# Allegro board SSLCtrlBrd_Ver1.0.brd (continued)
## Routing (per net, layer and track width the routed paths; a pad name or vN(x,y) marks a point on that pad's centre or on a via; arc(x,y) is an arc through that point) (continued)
N16217582: length 4.1
  TOP w0.152: C15.1 44.4,36.83 44.4,34.82 43.99,34.42 U4.2
N16217594: length 2.2
  TOP w0.152: U4.6 40.4,31.82 C19.1
N16217668: length 2.3
  TOP w0.152: U4.4 40.65,33.12 C17.1
N16217676: length 4.4
  TOP w0.152: U4.3 41.6,33.77 41.15,34.21 39.5,34.21 C11.2
N16217680: length 2.2
  TOP w0.152: U4.1 40.4,35.07 C11.1
N16217684: length 4.2
  TOP w0.152: C17.2 39.5,32.59 40.95,32.59 41.07,32.47 U4.5
N16222454: length 11.5
  TOP w0.152: D4.2 93.42,57.06 v1(93.42,57.89) ; D4.2 94.97,57.01 R28.1 C46.1 95.46,56.16 96.83,56.16 97.14,55.85 U18.1 ; D4.2 93.26,56.9 91.77,56.9 91.06,56.18 J5.2
  BOTTOM w0.152: TP6.1 v1(93.42,57.89)
N16222490: length 9.3
  TOP w0.152: v1(51.63,9.02) 50.98,9.66 49.75,9.66 49.14,10.27 U10.8
  BOTTOM w0.152: RP2.1 RP1.8 51.63,9.99 v1(51.63,9.02)
N16222522: length 6.9
  TOP w0.152: v1(52.44,9.06) 52.44,10.12 51.68,10.88 U10.7
  BOTTOM w0.152: RP1.7 52.43,9.06 v1(52.44,9.06) 52.43,9.05 RP2.2
N16222576: length 7
  TOP w0.152: U10.6 54.22,11.11 53.25,10.15 v1(53.25,9.06)
  BOTTOM w0.152: RP2.3 53.25,9.05 v1(53.25,9.06) 53.25,9.06 RP1.6
N16222640: length 8.6
  TOP w0.152: U10.5 56.76,10.2 56.19,9.63 54.64,9.63 v1(54.07,9.06)
  BOTTOM w0.152: RP2.4 54.06,9.05 v1(54.07,9.06) 54.06,9.06 RP1.5
N16223004: length 5.5
  TOP w0.305: R20.2 133.92,16.74 U14.1 R22.1
N16223050: length 6.2
  TOP w0.152: J7.1 12.45,96.42 R30.1
  BOTTOM w0.152: J7.1 11.39,97.52 TP7.1
N16223096: length 5.5
  TOP w0.152: U20.3 56.16,46.15 R39.2 57.84,46.61 C49.1 R41.2
N16223166: length 4.5
  TOP w0.254: R19.1 45.39,48.5 R18.2 45.62,50.38 U9.4
N16223316: length 4.4
  BOTTOM w0.152: TP8.1 9.97,96.09 J7.2 11.45,94.6 Q3.3
N16223472: length 3.2
  TOP w0.33: U9.1 46.94,54.19 45.95,53.2 C34.2
N16223708: length 8.4
  TOP w0.305: R24.1 U14.2 131.21,15.67 133,13.89 R21.2
N16223800: length 16.8
  TOP w0.305: C43.1 128.25,13.19 ; 128.25,13.19 133.67,13.19 134.29,12.57 136.6,12.57 136.95,12.92 R21.1 R20.1 136.31,16.02 Q2.3 ; 128.25,13.19 U14.4
N16223854: length 1.6
  TOP w0.254: R42.1 D6.1
N16223890: length 21.9
  TOP w0.152: v1(56.82,17.09) 74.27,17.09 v1(75.02,16.35)
  BOTTOM w0.152: U13.9 76.34,16.35 v1(75.02,16.35) ; U11.10 v1(56.82,17.09)
N16224232: length 1.9
  TOP w0.152: U16.1 109.05,41.83 R26.1
N16224936: length 62.6
  TOP w0.203: v1(121.13,49.68) 121.13,43.51 127.03,37.62 130.23,37.62 U22.3
  BOTTOM w0.152: J9.6 132.92,82.42 127,76.5 121.9,76.5 120.3,74.9 120.3,61.99 118.24,59.93 118.24,57 120.37,54.86 120.37,52.3 119.46,51.38 119.46,50.11 119.89,49.68 121.13,49.68 v1(121.13,49.68)
N16225198: length 3.2
  BOTTOM w0.152: R32.2 15.14,92.39 R33.2 14.09,93.45 Q3.1
N16225308: length 6.4
  BOTTOM w0.254: TP9.1 J8.1 C50.1 R36.1
N16225518: length 4.9
  BOTTOM w0.254: R40.2 J8.3 TP10.1
N16225732: length 1.7
  TOP w0.152: R27.1 109.07,46.84 U17.1
N16226050: length 2.3
  TOP w0.152: D3.1 95.89,38.1 R23.1
N16226124: length 3.3
  TOP w0.152: R34.1 57.86,43.21 R37.2 56.21,43.23 U20.1
N16231004: length 12.9
  BOTTOM w0.152: RP7.6 51.89,97.87 51.49,97.46 TP14.1 51.44,95.53 J10.2 51.44,92 51.67,91.77 53.9,91.77 55.22,90.45 RP8.8
N16231012: length 16.7
  BOTTOM w0.152: RP7.7 50.42,98.68 49.05,97.31 TP15.1 48.94,95.47 J10.3 48.94,92.95 50.47,91.41 53.44,91.41 54.41,90.45 RP8.7
N16231068: length 21.6
  BOTTOM w0.152: RP7.8 47.8,99.49 46.41,98.09 TP16.1 46.41,93.42 J10.4 46.44,93.16 48.57,91.03 52.81,91.03 53.6,90.25 RP8.6
N16231202: length 12
  BOTTOM w0.152: RP9.6 111.05,97.41 110.64,97 TP22.1 110.64,93.48 111.99,92.13 114.3,92.13 114.89,91.54 RP10.8
N16231224: length 16.3
  BOTTOM w0.152: RP9.7 109.25,98.22 108.21,97.18 TP23.1 108.21,93.43 J12.3 109.9,91.72 113.49,91.72 114.07,91.14 RP10.7
N16231228: length 21.1
  BOTTOM w0.152: RP9.8 107.01,99.03 105.7,97.73 TP24.1 105.7,93.42 105.7,93.42 107.81,91.31 113.08,91.31 113.26,91.14 RP10.6
N16231344: length 5
  BOTTOM w0.152: J13.2 121.9,92.87 R70.2
  BOTTOM w0.254: TP28.1 123.4,96.28 J13.2
N16231348: length 53.2
  TOP w0.152: U28.3 105.29,44.78 105.89,45.39 105.89,54.03 v1(106.07,54.2)
  BOTTOM w0.152: v1(106.07,54.2) 106.66,54.79 106.66,64.21 113.01,70.56 113.01,75.64 120.06,82.69 D19.3 120.06,89.9 R71.1
N16231352: length 4.8
  BOTTOM w0.152: J13.4 120.42,93.36 R71.2
  BOTTOM w0.254: J13.4 119.4,96.31 TP29.1
N16231410: length 33.7
  TOP w0.152: v2(108.92,85.88) 108.97,85.88 109.02,85.83 ; C64.2 113.68,71.82 124.61,82.75 124.61,87.15 123.6,88.16 120.86,88.16 120.83,88.19
  TOP w0.254: C64.2 107.94,70.39 C68.2 107.82,70.21 107.24,70.21 106.43,71.02 U26.11
  vias: v2(93.35,86.64) v2(93.32,86.03) v2(93.98,86.66) v2(93.98,86.03) v2(94.67,86.64) v2(94.62,86) v2(99.52,86.74) v2(99.49,86) v2(100.23,86.74) v2(100.26,86) v2(100.94,86.72) v2(100.97,85.98) v2(106.07,86.66) v2(106.07,85.95) v2(106.78,86.66) v2(106.78,85.93) v2(107.47,85.95) v2(107.5,86.64) v2(108.08,88.77) v2(108.1,88.09) v2(108.1,87.4) v2(108.18,85.95) v2(108.21,86.64) v2(108.79,88.77) v2(108.79,88.09) v2(108.82,87.38) v2(108.94,86.61)
N16231448: length 7.4
  TOP w0.152: C66.2 109.45,65.13 R62.2 108.64,67.36 107.04,67.36 106.15,68.25 106.15,69.27 105.9,69.52 U26.8
N16231582: length 55.7
  TOP w0.152: v1(106.66,53.52) 106.28,53.14 106.28,44.73 104.45,42.9 U28.1
  BOTTOM w0.152: R70.1 121.9,89.6 D18.3 122.52,84.42 113.44,75.34 113.44,70.31 107.11,63.98 107.11,53.98 v1(106.66,53.52)
N16231708: length 24.7
  TOP w0.254: Q5.2 v1(39.12,78.87) ; v1(38.64,73.41) 37.54,73.41 37.27,73.13 U23.15
  BOTTOM w0.254: v1(39.12,78.87) 38.03,77.77 31.5,77.77 30.94,77.22 30.94,75.26 32.79,73.41 v1(38.64,73.41)
N16231980: length 3.4
  TOP w0.152: C63.2 107.34,68.17 106.63,68.88 106.63,69.42 106.04,70.02 U26.9
N16231984: length 5.2
  TOP w0.152: U26.10 106.04,70.52 106.18,70.37 106.19,70.37 106.99,69.57 106.99,69.14 107.16,68.96 108.6,68.96 C63.1
N16232020: length 3.4
  TOP w0.152: U26.25 100.07,71.02 99.54,71.55 99.54,72.67 99.26,72.95 R59.2
N16232070: length 13.7
  TOP w0.152: R62.1 R61.2 104.8,66.55 104.35,66.09 ; 103.3,66.09 102.34,66.09 102.06,66.37 102.06,67.21 101.88,67.39 101.88,67.92 102.02,68.05 U26.2 ; 103.3,66.09 104.35,66.09 ; 103.3,66.09 103.02,66.38 U26.4 ; 104.35,66.09 104.27,66.17 104.27,67.82 104.02,68.07 U26.6
N16232434: length 2.4
  TOP w0.152: C64.1 106.73,71.82 106.43,71.53 105.44,71.53 U26.12
N16232510: length 3.6
  TOP w0.254: R60.2 94.59,81.97 Q7.4
N16232530: length 8.8
  TOP w0.254: R60.1 97.36,76.73 99.37,74.73 100.99,74.73 101.48,74.24 101.48,73.42 U26.21
N16232652: length 4.5
  TOP w0.254: R63.1 100.84,76.05 101.09,75.79 102.03,75.79 102.52,75.31 U26.19
N16232660: length 3.7
  TOP w0.254: Q8.4 100.84,81.97 R63.2
N16232730: length 7.7
  BOTTOM w0.254: R57.2 25.58,99.85 28.27,97.16 TP20.1 28.23,96.24 J11.2
N16232734: length 68.2
  TOP w0.152: U25.3 42.17,43.79 v1(41.07,44.88)
  BOTTOM w0.152: R58.1 22.25,98.22 21.24,97.21 D13.3 20.94,95.87 29.49,87.33 29.49,68.74 30.89,67.34 30.89,65.74 32.79,63.83 34.01,63.83 41.51,56.34 41.51,48.08 41.07,47.65 v1(41.07,44.88)
N16232738: length 4
  BOTTOM w0.254: J11.4 24.23,96.29 TP21.1 24.51,96.57 R58.2
N16232790: length 5.9
  TOP w0.254: R64.1 104.9,76.56 103.52,75.17 U26.17
N16232794: length 3.8
  TOP w0.254: Q9.4 107.04,81.97 R64.2
N16232838: length 19.7
  TOP w0.254: U26.16 104.02,74.4 v1(104.5,74.88) ; Q7.2 v1(92.09,78.38)
  BOTTOM w0.254: v1(104.5,74.88) 104.5,75.84 102.57,77.77 96.98,77.77 96.37,78.38 v1(92.09,78.38)
N16232850: length 14.4
  TOP w0.254: Q8.2 v1(98.27,78.51) ; v1(105.21,74.45) 104.52,73.76 U26.15
  BOTTOM w0.254: v1(98.27,78.51) 98.3,78.54 102.64,78.54 105.29,75.9 105.29,74.52 v1(105.21,74.45)
N16232866: length 11.4
  TOP w0.254: v1(106.48,73.15) 106.48,72.85 106.15,72.52 105.43,72.52 U26.14 ; Q9.2 v1(104.47,78.82)
  BOTTOM w0.254: v1(104.47,78.82) 104.8,78.82 106.48,77.14 v1(106.48,73.15)
N16232926: length 5.5
  TOP w0.254: R69.2 109.4,77.75 R68.2
  TOP w0.305: v3(108.51,79.78) 109.65,78.64 R69.2
  vias: v2(89.97,80.54) v2(89.94,79.88) v2(90.02,81.92) v2(89.99,81.23) v2(90.78,80.59) v2(90.76,79.88) v2(96.14,80.26) v2(96.22,82.22) v2(96.27,81.58) v2(96.19,80.98) v2(96.78,80.06) v2(96.93,80.7) v2(102.36,82.04) v2(102.34,81.36) v2(102.34,80.62) v2(102.31,79.86) v2(102.95,79.88) v2(103.02,80.65)
N16233028: length 4.3
  TOP w0.152: C69.2 106.91,72.55 106.91,72.54 106.39,72.02 U26.13
  TOP w0.254: C69.2 107.72,74.85 R68.1
N16233226: length 23.9
  TOP w0.254: U24.1 54.97,76.17 46,76.17 44.02,74.19 44.02,71.96 43.06,71 C55.2
  TOP w0.305: C55.2 40.69,69.55 C59.2 40.44,69.2 39.5,70.14 U23.11
  vias: v2(34.22,86.97) v2(34.19,86.26) v2(34.9,86.94) v2(34.9,86.23) v2(35.59,86.94) v2(35.59,86.23) v2(40.34,86.97) v2(40.34,86.28) v2(41.05,86.97) v2(41.02,86.26) v2(41.76,86.97) v2(41.73,86.28) v2(46.66,86.92) v2(46.64,86.21) v2(47.35,86.89) v2(47.32,86.18) v2(48.03,86.92) v2(48.03,86.18) v2(48.62,88.65) v2(48.62,87.91) v2(48.72,86.92) v2(48.72,86.16) v2(49.33,88.65) v2(49.33,87.91) v2(49.33,86.89) v2(49.33,86.13)
N16233284: length 7.2
  TOP w0.254: U23.8 38.54,68.64 38.79,68.39 38.79,67.5 39.83,66.46 41.28,66.46 R49.2 C57.2
N16233424: length 70.4
  TOP w0.152: U25.1 v1(40.41,45.67)
  BOTTOM w0.152: R57.1 D12.3 20.2,99.1 20.2,95.86 28.93,87.12 28.93,68.33 30.48,66.78 30.48,65.46 32.57,63.37 33.76,63.37 41.1,56.03 41.1,48.54 40.41,47.85 v1(40.41,45.67)
N16233882: length 3.5
  TOP w0.254: U23.9 38.88,69.14 39.27,68.74 39.27,68.03 40.01,67.29 C54.2
N16233886: length 5.3
  TOP w0.254: U23.10 39.16,69.64 39.75,69.05 39.75,68.37 39.97,68.16 41.28,68.16 C54.1
N16233926: length 3.4
  TOP w0.152: U23.25 32.83,70.14 32.36,70.61 32.36,71.68 32.11,71.93 31.56,71.93 R46.2
N16233960: length 14.3
  TOP w0.152: 37.34,64.9 37.21,65.02 37.21,66.22 36.77,66.66 U23.6 ; 37.34,64.9 38.28,64.9 R48.2 ; 37.34,64.9 35.89,64.9 ; U23.4 35.77,67.18 35.89,67.06 35.89,64.9 ; 35.89,64.9 35.61,64.9 34.77,65.74 U23.2
  TOP w0.305: R48.2 39.06,65.59 R49.1
N16234200: length 2.4
  TOP w0.254: U23.12 39.44,70.64 39.8,71 C55.1
N16234296: length 6.3
  TOP w0.254: U23.21 34.27,73.48 33.53,74.22 33.53,76.2 34.42,77.09 R47.1
N16234430: length 9.6
  TOP w0.254: R50.1 40.62,76.15 36.71,76.15 35.26,74.7 35.26,72.51 U23.19
N16234438: length 3.4
  TOP w0.254: R50.2 41.66,78.87 Q5.4
N16234556: length 13
  TOP w0.254: R51.1 45.75,78.36 42.62,75.23 37.95,75.23 36.27,73.55 U23.17
N16234560: length 3.8
  TOP w0.254: Q6.4 47.86,82.14 R51.2
N16234618: length 16.7
  TOP w0.254: v1(38.03,74.24) 37.7,74.24 36.77,73.32 U23.16 ; v1(31.73,76.28) 31.73,76.33 32.88,77.48 Q4.2
  BOTTOM w0.254: v1(38.03,74.24) 37.67,73.89 33.4,73.89 31.73,75.57 v1(31.73,76.28)
N16234658: length 14
  TOP w0.254: v1(44.1,77.88) 45.35,79.13 Q6.2 ; U23.14 38.9,71.64 39.19,71.93 v1(39.19,72.49)
  BOTTOM w0.254: v1(39.19,72.49) 39.19,73 44.07,77.88 v1(44.1,77.88)
N16234708: length 11.7
  TOP w0.305: R52.2 42.76,73.95 45.65,76.84 49.35,76.84 R56.2 v3(50.47,79.68)
  vias: v2(30.84,82.37) v2(30.84,81.64) v2(30.84,80.87) v2(30.81,80.16) v2(31.57,80.87) v2(31.55,80.16) v2(37.01,82.52) v2(37.01,81.84) v2(37.01,81.15) v2(37.01,80.44) v2(37.8,80.85) v2(37.8,80.14) v2(43.26,82.45) v2(43.26,81.76) v2(43.28,81.08) v2(43.26,80.39) v2(44.05,80.9) v2(44.05,80.21)
N16234816: length 4.3
  TOP w0.254: U23.13 39.13,71.14 C60.2 R52.1
N16242851: length 12.1
  BOTTOM w0.152: RP11.6 142.14,51.23 141.48,51.89 TP30.1 ; J20.2 136.65,50.63 136.65,48.03 136.32,47.7 RP12.8
  BOTTOM w0.203: J20.2 140.24,51.94 TP30.1
N16242877: length 21.6
  BOTTOM w0.152: TP32.1 142.75,56.97 143.77,55.96 RP11.8 ; 134.97,49.33 135.71,49.33 135.84,49.45 135.84,54.81 J20.4
  BOTTOM w0.203: J20.4 140.26,56.94 TP32.1
N16242881: length 16.7
  BOTTOM w0.152: J20.3 136.25,52.72 136.25,48.67 136.1,48.51 RP12.7 ; RP11.7 142.95,53.31 141.94,54.33 TP31.1
  BOTTOM w0.203: TP31.1 140.18,54.44 J20.3
N16242947: length 9.4
  BOTTOM w0.152: RP13.6 8.21,65.1 8.82,64.49 TP38.1 12.05,64.49 J15.2 13.07,63.47 RP14.8
N16242969: length 12.4
  BOTTOM w0.152: RP13.7 7.39,63.12 8.66,61.85 TP39.1 12.01,61.85 J15.3 12.82,62.66 RP14.7
N16242981: length 16.3
  BOTTOM w0.152: RP14.6 14.12,61.85 12.1,59.82 J15.4 9.66,59.44 TP40.1 8.28,59.41 6.58,61.11 RP13.8
N16243085: length 55.5
  TOP w0.152: v1(40.9,41.53) 43.03,39.4 U34.3
  BOTTOM w0.152: R97.1 17.38,74.85 17.67,74.56 D31.3 17.77,74.14 19.1,74.14 19.11,74.13 26.12,74.13 27.97,72.29 27.97,67.74 29.26,66.45 29.26,65.41 32.23,62.43 33.38,62.43 40.11,55.7 40.11,49.48 39.09,48.46 39.09,43.28 40.85,41.53 v1(40.9,41.53)
N16243089: length 6.1
  BOTTOM w0.152: R96.2 11.94,76.28 J16.2 ; J16.2 11.18,77.04 ; J16.2 11.17,77.04 TP44.1
N16243107: length 6.7
  BOTTOM w0.152: R97.2 13.16,74.85 11.34,73.03 J16.4 8.93,73.03 TP45.1
N16243155: length 23.4
  TOP w0.152: C82.2 32.03,58.42 C86.2 33.63,56.05 32.99,55.41 32.99,54.58 U32.11
  TOP w0.254: 19.61,67.97 19.66,67.92 25.99,67.92 31.87,62.04 C82.2
  vias: v2(16.05,59.28) v2(16.74,59.28) v2(17.43,59.28) v2(17.58,58.47) v2(17.58,57.79) v2(17.58,57.1) v2(17.53,52.43) v2(17.55,51.71) v2(17.55,51.03) v2(17.66,46.1) v2(17.63,45.39) v2(17.63,44.68) v2(18.11,59.26) v2(18.26,58.47) v2(18.26,57.79) v2(18.26,57.1) v2(18.24,52.43) v2(18.24,51.69) v2(18.24,50.98) v2(18.37,46.1) v2(18.34,45.39) v2(18.34,44.68) v2(18.82,59.23) v2(18.95,58.47) v2(18.95,57.79) v2(18.95,57.1)
N16243193: length 6.9
  TOP w0.152: U32.8 34.38,54.88 34.75,55.25 35.51,55.25 36.2,55.93 36.2,57.58 R88.2 38.46,58.37 C84.2
N16243319: length 54.7
  TOP w0.152: U34.1 42.75,41.28 v1(41.33,42.7)
  BOTTOM w0.152: v1(41.33,42.7) 41.2,42.7 39.68,44.22 39.68,48.18 40.64,49.15 40.64,55.8 33.56,62.89 32.41,62.89 30.08,65.23 30.08,66.29 28.42,67.95 28.42,72.54 24.28,76.68 D30.3 17.26,76.28 R96.1
N16243721: length 4.8
  TOP w0.152: C81.1 34.65,57.57 34.65,56.16 34.5,56.01 34.45,56.01 34.44,55.99 34.33,55.99 33.38,55.05 U32.10
N16243729: length 3.1
  TOP w0.152: C81.2 35.41,56.16 34.85,55.6 34.44,55.6 33.88,55.04 U32.9
N16243757: length 4.2
  TOP w0.152: U32.25 32.88,49.14 32.39,48.64 31.31,48.64 R85.2
N16243811: length 15
  TOP w0.152: 38.2,53.26 38.2,54 R87.2 36.98,55.27 R88.1 ; 38.2,53.26 38.18,53.24 36.83,53.24 36.65,53.06 U32.6 ; 38.2,53.26 38.2,51.74 ; U32.2 35.97,51.06 36.1,50.93 37.7,50.93 38.2,51.44 38.2,51.74 ; U32.4 36.95,52.06 37.16,51.84 38.1,51.84 38.2,51.74
N16244015: length 2.5
  TOP w0.152: U32.12 32.38,56.23 C82.1
N16244099: length 3.2
  TOP w0.254: Q13.4 25.59,45.96 R86.2
N16244111: length 7.2
  TOP w0.254: U32.21 28.33,50.56 27.28,49.5 R86.1
N16244229: length 3.3
  TOP w0.254: Q14.4 25.58,52.17 R89.2
N16244237: length 3.4
  TOP w0.254: U32.19 28.89,51.56 28.32,52.12 R89.1
N16244299: length 4.2
  BOTTOM w0.203: TP36.1 138.96,75.03 J14.2 138.93,75.06 R83.2
N16244311: length 5.8
  BOTTOM w0.152: TP37.1 138.99,79.07 J14.4 137.74,79.03 136.87,78.17 R84.2
N16244315: length 70
  TOP w0.152: v1(119.53,42.34) 119.23,42.65 119.23,50.32 v1(120.07,51.16) ; U31.3 104.57,40.23 106.61,38.2 117.58,38.2 118.59,39.22 v1(118.59,39.45)
  BOTTOM w0.152: v1(119.53,42.34) 119.03,41.83 119.03,39.88 v1(118.59,39.45) ; D25.3 129.22,77.51 127.69,75.97 122.33,75.97 120.7,74.35 120.7,61.89 118.62,59.81 118.62,57.2 120.73,55.09 120.73,51.82 v1(120.07,51.16)
  BOTTOM w0.203: D25.3 134.7,77.51 R84.1
N16244363: length 7.8
  TOP w0.254: R90.1 27.18,54.69 29.29,52.58 30.5,52.58 U32.17
N16244387: length 3.2
  TOP w0.254: Q15.4 25.43,58.37 R90.2
N16244447: length 17.3
  TOP w0.254: v1(25.53,43.41) 22.39,43.41 Q13.2 ; v1(29.31,53.52) 29.77,53.06 U32.16
  BOTTOM w0.254: v1(25.53,43.41) 26.8,44.68 26.8,52.91 27.21,53.31 29.11,53.31 v1(29.31,53.52)
N16244471: length 12.5
  TOP w0.254: Q14.2 v1(26.01,49.63) ; v1(28.75,54.13) 28.83,54.2 29.82,54.2 U32.15
  BOTTOM w0.254: v1(28.75,54.13) 28.65,54.23 26.9,54.23 26.01,53.34 v1(26.01,49.63)
N16244479: length 9.8
  TOP w0.254: v1(30.79,55.35) 31.38,54.75 U32.14 ; Q15.2 v1(25.55,55.83)
  BOTTOM w0.254: v1(30.79,55.35) 30.3,55.83 v1(25.55,55.83)
N16244549: length 4.6
  TOP w0.254: v3(25.61,59.72) 26.11,60.22 R95.2 28.91,59 R94.2
  vias: v2(22.33,53.75) v2(22.35,47.65) v2(22.35,41.28) v2(23.04,53.75) v2(23.04,47.65) v2(23.04,41.28) v2(23.78,54.51) v2(23.75,53.75) v2(23.75,47.63) v2(23.75,42.16) v2(23.75,41.28) v2(23.8,48.36) v2(24.49,54.51) v2(24.46,53.75) v2(24.46,42.16) v2(24.49,41.28) v2(24.51,48.34) v2(24.51,47.63)
N16244649: length 4.4
  TOP w0.152: U32.13 31.88,55.25 C87.2 R94.1
N16244783: length 21.4
  TOP w0.203: U29.11 116.75,57.92 115.99,57.16
  TOP w0.305: v2(130.58,55.45) 128.78,53.64 120.78,53.64 120.04,52.91 118.19,52.91 117.35,53.75 C75.2 115.67,56.39 C73.2 115.5,56.67 115.99,57.16
  vias: v2(130.58,56.85) v2(130.61,69.34) v2(130.61,68.63) v2(130.63,67.92) v2(130.66,63.14) v2(130.66,62.43) v2(130.66,61.75) v2(130.61,56.16) v2(131.32,69.37) v2(131.32,68.66) v2(131.35,67.97) v2(131.37,63.09) v2(131.37,62.41) v2(131.35,61.72) v2(131.29,56.85) v2(131.29,56.13) v2(131.29,55.45)
N16244821: length 7
  TOP w0.152: C72.2 111.05,57.3 R75.2 112.85,58.37 113.63,59.14 U29.8
N16244917: length 68.3
  TOP w0.152: v1(119.66,39.27) 118.16,37.77 106.2,37.77 105.62,38.35 U31.1 ; v1(120.14,50.37) v1(120.14,41.61)
  BOTTOM w0.152: v1(120.14,41.61) 119.66,41.12 v1(119.66,39.27) ; v1(120.14,50.37) 121.08,51.31 121.08,55.34 119,57.42 119,59.69 121.13,61.82 121.13,74.14 122,75.01 134,75.01 D24.3
  BOTTOM w0.203: R83.1 D24.3
N16245297: length 6.1
  TOP w0.152: U29.10 116.25,58.24 115.65,57.63 114.68,57.63 114.43,57.38 114.43,55.47 C74.1
N16245309: length 4.3
  TOP w0.152: C74.2 113.69,56.41 113.69,57.48 114.2,57.99 115.32,57.99 115.75,58.42 U29.9
N16245341: length 3.5
  TOP w0.152: R72.2 118.4,66.1 117.03,64.73 117.01,64.73 116.86,64.58 116.86,64.56 116.75,64.45 U29.25
N16245371: length 10.8
  TOP w0.152: U29.6 112.68,60.55 112.17,60.05 R75.1 R74.2 112.24,61.62 112.68,62.05 ; 112.68,62.05 113.24,61.49 113.72,61.49 113.78,61.55 U29.4 ; 112.68,62.05 112.68,62.08 113.26,62.66 113.69,62.66 113.8,62.55 U29.2
N16245565: length 2.8
  TOP w0.152: C75.1 117.25,56.49 U29.12
N16245657: length 5.3
  TOP w0.254: R73.1 120.27,66.78 120.27,63.86 119.47,63.05 U29.21
N16245661: length 4.3
  TOP w0.254: R73.2 124.46,67.39 125.07,68 126.49,68 Q10.4
N16245779: length 4.2
  TOP w0.254: R76.2 123.52,62.08 123.85,61.75 126.45,61.75 Q11.4
N16245787: length 1.8
  TOP w0.254: U29.19 120.83,62.05 R76.1
N16245901: length 5.9
  TOP w0.254: R77.2 122.48,57.15 124,55.63 126.51,55.63 Q12.4
N16245905: length 5
  TOP w0.254: R77.1 121.54,59.13 121.54,60.38 121.16,60.76 120.16,60.76 119.86,61.05 U29.17
N16245981: length 16.7
  TOP w0.152: U29.16 119.76,60.55 120.12,60.2 120.4,60.2 v1(120.58,60.02)
  TOP w0.254: Q10.2 v1(123.28,70.6)
  BOTTOM w0.254: v1(123.28,70.6) 121.72,69.04 121.72,61.34 120.58,60.2 v1(120.58,60.02)
N16246009: length 12
  TOP w0.152: U29.15 119.73,60.05 119.94,59.84 119.94,59.23
  TOP w0.254: 119.94,59.23 v1(119.97,59.21) ; Q11.2 v1(123.31,64.38)
  BOTTOM w0.254: v1(123.31,64.38) 123.29,64.36 122.89,64.36 122.25,63.73 122.25,60.71 120.75,59.21 v1(119.97,59.21)
N16246065: length 9.1
  TOP w0.254: Q12.2 v1(124.16,58.14) ; v1(119.71,58.04) 118.82,58.04 118.25,58.61 U29.14
  BOTTOM w0.254: v1(119.71,58.04) 124.06,58.04 v1(124.16,58.14)
N16246163: length 3.8
  TOP w0.254: R81.2 R82.2
  TOP w0.305: R82.2 v3(124.36,54.71)
  vias: v2(124.39,72.69) v2(124.34,66.45) v2(124.36,65.68) v2(124.36,60.25) v2(124.39,59.49) v2(124.41,71.93) v2(125.05,66.45) v2(125.07,65.71) v2(125.07,60.25) v2(125.1,72.69) v2(125.12,71.96) v2(125.1,59.51) v2(125.76,66.42) v2(125.78,60.22) v2(125.81,72.67) v2(126.47,66.42) v2(126.52,72.67) v2(126.49,60.22)
N16246325: length 4.9
  TOP w0.152: R81.1 C78.2 118.98,57.18 117.75,58.4 U29.13
N16248666: length 12.7
  BOTTOM w0.152: RP15.6 81.64,97.61 81.16,97.13 TP46.1 81.16,93.59 J17.2 81.09,92.62 81.38,92.33 84.64,92.33 85.24,91.72 RP16.8
N16248688: length 17.4
  BOTTOM w0.152: RP16.7 84.43,91.31 83.82,91.92 79.35,91.92 78.59,92.68 J17.3 78.72,93.65 TP47.1 78.72,97.99 79.15,98.43 RP15.7
N16248692: length 21.5
  BOTTOM w0.152: RP15.8 77.24,99.24 76.08,98.07 TP48.1 76.09,96.17 J17.4 78.11,91.52 83.21,91.52 83.62,91.11 RP16.6
N16248822: length 13.4
  TOP w0.254: U36.1 85.02,77.04 85.02,73.41 83.29,71.68 C92.2
  TOP w0.305: C92.2 80.54,70.23 C94.2 80.29,69.88 79.35,70.82 U35.11
  vias: v2(63.5,86.89) v2(63.5,86.21) v2(64.19,86.89) v2(64.19,86.18) v2(64.9,86.89) v2(64.9,86.18) v2(69.75,86.89) v2(69.75,86.21) v2(70.46,86.89) v2(70.44,86.18) v2(71.15,86.89) v2(71.15,86.18) v2(76.08,86.74) v2(76.05,86.03) v2(76.79,86) v2(76.81,86.74) v2(77.55,86.74) v2(77.52,86) v2(78.16,88.29) v2(78.16,87.58) v2(78.23,86.72) v2(78.21,85.98) v2(78.87,88.29) v2(78.87,87.58) v2(78.92,86.72) v2(78.92,86.03)
N16248876: length 7.2
  TOP w0.254: C91.2 R101.2 81.13,67.13 79.68,67.13 78.64,68.18 78.64,69.06 78.39,69.32 U35.8
N16249066: length 3.5
  TOP w0.254: C90.2 79.86,67.97 79.12,68.71 79.12,69.42 78.73,69.82 U35.9
N16249070: length 5.3
  TOP w0.254: U35.10 79.01,70.32 79.6,69.72 79.6,69.05 79.82,68.84 81.13,68.84 C90.1
N16249094: length 3.4
  TOP w0.152: R98.2 71.86,72.75 72.14,72.47 72.14,71.35 72.67,70.82 U35.25
N16249128: length 10.9
  TOP w0.152: U35.4 75.62,67.62 75.69,67.54 75.69,66.73 ; 76.81,66.85 76.81,67.18 76.81,67.64 76.62,67.84 U35.6 ; 76.81,66.85 76.68,66.73 75.69,66.73 ; 76.81,66.85 77.29,66.37 R100.2 ; 75.69,66.73 74.88,66.73 74.55,67.06 74.55,67.75 74.62,67.82 U35.2
  TOP w0.254: R101.1 78.92,66.27 R100.2
N16249326: length 2.4
  TOP w0.254: U35.12 79.29,71.32 79.66,71.68 C92.1
N16249418: length 3.4
  TOP w0.254: R99.2 64.82,78.69 Q16.4
N16249422: length 11.1
  TOP w0.254: U35.21 74.12,73.54 73.1,74.55 68.56,74.55 66.12,76.99 R99.1
N16249556: length 7
  TOP w0.254: U35.19 75.12,74.64 73.99,75.77 71.53,75.77 71.05,76.25 71.05,76.99 R102.1
N16249564: length 3.4
  TOP w0.254: Q17.4 71.01,78.7 R102.2
N16249674: length 4.3
  TOP w0.254: U35.17 76.12,75.15 77.19,76.23 77.19,76.94 R103.1
N16249706: length 22.6
  TOP w0.254: v2(77.41,75.15) 77.41,75.14 76.62,74.35 U35.16 ; Q16.2 v1(62.28,78.13)
  BOTTOM w0.254: v1(62.28,78.13) 64.72,75.69 76.86,75.69 v2(77.41,75.15)
N16249718: length 17.4
  TOP w0.254: v2(77.59,74.31) 77.58,74.31 77.12,73.84 U35.15 ; Q17.2 v1(68.47,78.22)
  BOTTOM w0.254: v2(77.59,74.31) 77.61,74.31 78.13,74.83 78.13,75.59 77.42,76.3 70.39,76.3 v1(68.47,78.22)
N16249734: length 13.3
  TOP w0.254: Q18.2 v1(74.67,78.47) ; v1(78.97,73.38) 78.97,72.67 78.62,72.32 U35.14
  BOTTOM w0.254: v1(74.67,78.47) 76.37,78.47 78.97,75.87 v1(78.97,73.38)
N16249780: length 5.8
  TOP w0.254: R108.2 82.07,75.64 R106.2
  TOP w0.305: R108.2 v3(79.81,79.63)
  vias: v2(60.28,82.42) v2(60.28,81.71) v2(60.25,80.98) v2(60.25,80.26) v2(61.01,80.77) v2(61.04,80.11) v2(66.47,81.69) v2(66.47,81) v2(66.47,80.31) v2(66.5,82.37) v2(67.29,80.75) v2(67.29,80.06) v2(72.65,82.14) v2(72.67,81.46) v2(72.67,80.77) v2(72.67,80.11) v2(73.36,80.77) v2(73.38,80.09)
N16249898: length 4.5
  TOP w0.254: 80.32,73.24 80.32,73.15 78.98,71.82 U35.13 ; 80.32,73.24 80.39,73.32 R106.1 ; 80.32,73.24 C96.2
N16251307: length 1.5
  TOP w0.152: D36.1 R114.2
N16252156: length 1.3
  TOP w0.254: R117.1 27.13,30.45 C102.2
N16252160: length 1.4
  TOP w0.254: C103.2 28.63,30.51 R118.1
N16252164: length 5.9
  TOP w0.254: R117.2 27.13,33.88 25.1,35.92 22.61,35.92 U39.3
N16252176: length 7.7
  TOP w0.254: U39.4 22.64,37.13 25.15,37.13 28.63,33.66 R118.2
N16252300: length 3.8
  TOP w0.254: C101.1 25.66,33.78 24.82,34.62 22.62,34.62 U39.2
N16254339: length 2.5
  TOP w0.152: C107.2 120.86,32.74 122.38,31.22 R121.1
N16254359: length 2.4
  TOP w0.152: C108.2 121.08,31.06 R123.1
N16254363: length 3.2
  TOP w0.152: U40.3 125.76,29.82 124.36,31.22 R121.2
N16254367: length 3.1
  TOP w0.152: R123.2 124.51,29.69 125.66,28.55 U40.4
N16254401: length 3.3
  TOP w0.152: U40.2 126.01,31.09 124.36,32.74 C106.1
N16258530: length 3.9
  BOTTOM w0.152: R120.1 R122.2 32.32,19.11 Q19.1
N16259236: length 2.8
  BOTTOM w0.152: R120.2 30.3,21 C105.2
N16260621: length 3.2
  TOP w0.305: FB2.1 14.41,33.37 U39.8
N16260625: length 3.1
  TOP w0.305: U39.5 14.01,37.18 FB3.1
N16260645: length 9.7
  TOP w0.305: FB3.2 9.31,37.13 4.35,32.16 J18.1
N16260657: length 8.3
  TOP w0.305: FB2.2 9.34,33.83 5.4,29.89 5.4,29.84
N16260735: length 5.2
  TOP w0.305: FB4.1 136.53,32.36 U40.8
N16260742: length 5.2
  TOP w0.305: U40.5 136.55,28.55 FB5.1
N16260748: length 7.7
  TOP w0.305: FB4.2 139.25,31.72 141.48,31.72 145.27,27.93 J19.2
N16260758: length 6.5
  TOP w0.305: J19.1 144.02,26.11 140.95,29.18 139.27,29.18 FB5.2
N16262221: length 1.5
  TOP w0.152: D37.1 R115.2
N16262712: length 16.9
  TOP w0.152: R115.1 42.24,11.38 v1(41.84,11.79) ; v1(41.56,20.35) 41.56,21.16 41.19,21.52 U38.13
  BOTTOM w0.152: v1(41.56,20.35) 41.56,20.34 41.56,12.06 v1(41.84,11.79)
N16262719: length 19.2
  TOP w0.152: U38.14 41.72,22.62 42.27,22.07 v1(42.27,20.98) ; v1(42.6,12.42) 42.62,12.42 43.03,12.02 43.03,7.97 R114.1
  BOTTOM w0.152: v1(42.6,12.42) 42.6,12.45 42.24,12.8 42.24,20.96 v1(42.27,20.98)
N16262726: length 10.8
  TOP w0.152: U38.1 40.66,8.32 40.96,8.02 40.96,2.22 41.3,1.89 D37.2 D36.2
N16265844: length 4
  TOP w0.152: R116.1 25.99,28.34 U38.17
N16266482: length 3.4
  TOP w0.152: U38.28 v1(27.89,12.72)
  BOTTOM w0.152: v1(27.89,12.72) 29.29,12.72 TP52.1
N16284199: length 8.1
  TOP w0.152: 64.94,9.02 v1(64.92,9.02) 63.75,9.02 62.45,10.33 U12.8
  BOTTOM w0.152: RP4.1 v1(64.92,9.02) RP3.8
N16284203: length 6.8
  TOP w0.152: U12.7 64.99,11 65.76,10.22 65.76,9.02 v1(65.75,9)
  BOTTOM w0.152: 65.73,8.99 v1(65.75,9) ; 65.73,8.99 RP3.7 ; 65.73,8.99 RP4.2
N16284207: length 6.8
  TOP w0.152: U12.6 67.53,10.99 66.56,10.02 66.56,9.01 v1(66.56,9)
  BOTTOM w0.152: 66.55,8.99 RP3.6 ; 66.55,8.99 RP4.3 ; 66.55,8.99 v1(66.56,9)
N16284215: length 8.4
  TOP w0.152: U12.5 70.07,10.33 68.75,9 v1(67.36,9)
  BOTTOM w0.152: 67.36,8.99 RP4.4 ; 67.36,8.99 RP3.5 ; 67.36,8.99 67.36,8.99 v1(67.36,9)
N16285416: length 11.3
  TOP w0.152: U15.8 75.76,10.03 76.36,9.42 77.52,9.42 v1(78.02,8.92)
  BOTTOM w0.152: TP5.1 77.97,8 RP6.1 v1(78.02,8.92) RP5.8
N16285420: length 7
  TOP w0.152: U15.7 78.3,10.48 78.86,9.91 v1(78.86,8.92)
  BOTTOM w0.152: 78.83,8.96 RP6.2 ; 78.83,8.96 v1(78.86,8.92) ; 78.83,8.96 RP5.7
N16285424: length 7.2
  TOP w0.152: U15.6 80.84,11.1 79.66,9.92 v1(79.66,8.92)
  BOTTOM w0.152: RP6.3 79.66,7.97 v1(79.66,8.92) 79.66,9.88 RP5.6
N16285432: length 8.8
  TOP w0.152: U15.5 83.38,10.34 82.56,9.52 81.06,9.52 v1(80.46,8.92)
  BOTTOM w0.152: RP5.5 80.46,9.89 v1(80.46,8.92) 80.46,7.96 RP6.4
N16299810: length 3.4
  TOP w0.254: Q4.4 35.42,78.78 R47.2
N16305767: length 3.4
  TOP w0.254: R103.2 77.21,78.7 Q18.4

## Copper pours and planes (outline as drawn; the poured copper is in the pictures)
+3V3 on TOP (solid shape): 67.49,74.2 67.49,70.89 67.85,70.54 69.93,70.54 69.98,70.49 69.98,66.8 71.07,65.71 71.35,65.71 71.38,65.74 73.28,65.74 73.79,65.23 73.79,62.13 72.82,61.16 68.79,61.16 68.48,61.47 68.48,68.96 68.02,69.42 65.99,69.42 65.41,68.83 65.41,65.84 65.03,65.46 63.96,65.46 63.58,65.84 63.58,69.01 62.26,70.33 62.26,74.96 62.33,75.03 66.66,75.03
+3V3 on POWER (solid shape): outline of 17657 points within 28.58,0.79 129.39,75.44
+5V on TOP (solid shape): 21.24,21.11 21.24,17.93 20.14,16.84 20.14,15.06 19.97,14.88 19.13,14.88 18.93,15.09 18.93,17.02 17.73,18.21 13.21,18.21 12.73,18.69 12.73,21.16 12.8,21.23 21.11,21.23
+5V on TOP (solid shape): 53.32,73.23 60.23,73.23 60.61,72.85 60.61,72.03 60.68,64.69 61.02,64.35 61.04,64.35 61.83,64.39 65.59,64.39 65.97,64.77 65.99,64.77 65.97,68.53 66.22,68.78 67.67,68.78 67.92,68.53 67.92,61.65 66.47,60.2 63.85,60.2 63.81,60.24 59.86,60.24 58.8,61.29 56.85,61.29 56.49,61.65 56.49,63.12 56.19,63.42 52.76,63.42 52.38,63.8 52.38,72.69 52.94,73.25 53.29,73.25
+5V on POWER (solid shape): outline of 13090 points within 0.43,3.34 149.66,105.21
GND on TOP (solid shape): 25.99,85.47 22.05,85.47 22.05,89.54 25.99,89.54
GND on TOP (solid shape): 63.02,68.47 63.02,65.47 62.91,65.37 61.39,65.37 61.26,65.5 61.26,68.47 61.42,68.62 62.86,68.62
GND on TOP (solid shape): 70.81,59.81 70.81,55.84 70.56,55.59 67.41,55.59 67.05,55.95 67.05,59.48 67.54,59.96 70.66,59.96
GND on TOP (solid shape): 55.17,83.39 55.17,77.57 54.49,76.89 51.87,76.89 51.87,76.91 51.59,77.19 51.59,83.31 51.87,83.59 54.97,83.59
GND on TOP (solid shape): 44.05,69.86 44.05,68.59 43.87,68.41 42.14,68.41 42.01,68.54 42.01,69.86 42.17,70.01 43.89,70.01
GND on TOP (solid shape): 83.87,83.85 83.87,77.04 83.77,76.94 81.41,76.94 80.9,77.44 80.9,80.04 80.01,80.92 80.01,83.59 80.37,83.95 83.77,83.95
GND on TOP (solid shape): 83.9,70.54 83.9,69.27 83.72,69.09 81.99,69.09 81.87,69.22 81.87,70.54 82.02,70.69 83.75,70.69
GND on TOP (solid shape): 111.3,70.74 111.3,69.47 111.12,69.29 109.39,69.29 109.27,69.42 109.27,70.74 109.42,70.89 111.14,70.89
GND on TOP (solid shape): 18.62,16.59 18.62,14.91 19.38,14.15 19.46,14.15 19.61,14 19.61,12.55 19.46,12.4 13.41,12.4 12.98,12.83 12.98,17.6 13.16,17.78 17.43,17.78
GND on TOP (solid shape): 52.3,54.47 52.3,52.31 52.53,52.09 54.53,52.09 54.89,51.73 54.89,51.27 54.71,51.1 52.53,51.1 52.35,50.92 52.35,50.14 52.25,50.04 49.58,50.04 49.45,50.17 49.45,54.65 49.53,54.73 52.04,54.73
GND on TOP (solid shape): 121.87,84.23 121.87,81.76 121.24,81.13 118.95,81.13 118.39,80.57 118.39,80.01 115.37,76.99 111.2,76.99 111.13,77.06 111.13,79.5 111.97,80.34 111.97,83.49 112.14,83.67 117.32,83.67 118.16,84.51 121.59,84.51
GND on TOP (solid shape): 56.13,62.42 56.13,61.2 56.46,60.87 58.62,60.87 59.51,59.99 63.7,59.99 64.03,59.66 64.03,50.61 63.55,50.13 59.03,50.13 58.65,50.51 58.65,55.29 58.22,55.72 55.57,55.72 54.89,56.4 51.99,56.4 51.71,56.68 51.71,62.6 52.02,62.91 55.65,62.91
GND on TOP (solid shape): 28.4,65 28.4,61.72 28.3,61.62 22.86,61.62 21.64,62.84 21.64,63.79 21.99,64.31 21.64,64.84 21.64,67.56 25.84,67.56
GND on TOP (solid shape): 28.4,76.66 28.4,68.01 28.21,68.01 27.44,68.77 27.45,68.79 26.47,69.24 26.92,68.26 26.94,68.27 27.91,67.29 28.4,67.29 28.4,66.26 28.34,66.16 28.23,66.18 26.13,68.28 21.64,68.28 21.64,77.27 21.9,77.52 27.54,77.52
GND on TOP (solid shape): 129,52.25 129.03,52.18 129,52.11 128.85,51.58 129.2,51.17 129.24,51.16 129.24,49.75 129.21,49.73 128.85,49.2 129.21,48.67 129.24,48.66 129.24,47.24 128.96,46.75 129.24,46.26 129.24,42.16 128.4,41.33 124,41.33 121.62,43.71 121.62,49.25 121.85,49.68 121.62,50.12 121.62,53.26 127.99,53.26
GND on GND (solid shape): outline of 29272 points within 0.41,0.79 149.71,105.21
VBAT on TOP (solid shape): 16.05,72.64 16.05,69.49 15.88,69.32 13.85,69.32 13.64,69.52 13.64,72.62 13.9,72.87 15.83,72.87
VBAT on TOP (solid shape): 125.83,92.33 125.83,90.02 125.61,89.79 121.87,89.79 121.64,90.02 121.64,92.43 121.82,92.61 125.55,92.61
VBAT on TOP (solid shape): 21.31,88.75 21.31,85.19 21.9,84.61 26.34,84.61 26.57,84.38 26.57,78.89 26.32,78.64 19.61,78.64 18.93,79.32 18.93,88.78 18.98,88.8 19.1,88.93 21.13,88.93
VBAT on TOP (solid shape): 140.08,44.42 140.08,41.2 140.1,41.19 139.25,40.34 134.65,40.34 134.39,40.59 134.39,41.28 134.75,41.63 137.42,41.63 137.92,42.14 137.92,44.42 138.1,44.6 139.91,44.6
VBAT on TOP (solid shape): 58.04,55.21 58.04,50.41 57.86,50.23 55.52,50.23 55.22,50.54 55.22,51.91 54.71,52.42 52.73,52.42 52.6,52.54 52.6,53.3 52.73,53.43 54.84,53.43 55.22,53.81 55.22,55.26 55.37,55.41 57.83,55.41
VBAT on TOP (solid shape): 91.68,78.73 91.66,78.69 91.56,78.33 91.72,78 91.72,76.58 91.57,76.43 87.84,76.43 87.66,76.61 87.66,78.66 87.86,78.87 91.54,78.87
VBAT on TOP (solid shape): 61.93,78.99 61.93,78.53 61.75,78.07 62.03,77.66 62.03,75.67 61.75,75.39 59.16,75.39 58.73,75.82 58.73,78.89 58.9,79.07 61.85,79.07
VBAT on POWER (solid shape): outline of 8190 points within 14.07,37.74 139.88,92.71
A_OUT_1 on TOP (solid shape): 34.85,83.03 34.85,79.91 34.8,79.86 33.53,79.86 33.48,79.91 33.48,83.03 33.53,83.08 34.8,83.08
A_OUT_1 on TOP (solid shape): 36.82,94.36 37.22,94.2 37.39,93.8 37.39,92.7 37.14,92.15 36.55,91.99 34.81,91.98 34.75,91.98 34.69,91.97 33.77,91.56 33.31,90.67 33.31,88.43 33.3,85.12 33.3,83.77 33.28,83.74 30.79,83.74 30.61,83.92 30.61,85.84 30.62,87.8 30.65,90.58 31.66,93.15 34.17,94.34 34.34,94.36 34.51,94.37
A_OUT_1 on BOTTOM (solid shape): 33.43,88.32 33.43,84.81 34.9,83.34 34.9,79.83 34.83,79.76 32.77,79.76 32.31,80.21 32.31,82.65 32.13,82.83 32.11,82.83 30.51,84.43 30.51,88.19 30.71,88.39 33.35,88.39
A_OUT_2 on TOP (solid shape): 94.03,82.91 94.03,79.78 93.98,79.73 92.71,79.73 92.66,79.78 92.66,82.91 92.71,82.96 93.98,82.96
A_OUT_2 on TOP (solid shape): 96.03,94.43 96.43,94.26 96.6,93.87 96.6,92.76 96.34,92.21 95.76,92.05 93.96,92.04 93.89,92.04 92.98,91.62 92.52,90.73 92.53,88.39 92.53,83.74 92.38,83.59 89.92,83.59 89.82,83.69 89.82,85.9 89.83,87.86 89.85,90.64 90.87,93.22 93.37,94.4 93.55,94.42 93.72,94.43
A_OUT_2 on BOTTOM (solid shape): 92.53,88.27 92.53,84.76 94.01,83.29 94.01,79.78 93.93,79.71 91.87,79.71 91.42,80.16 91.42,82.6 91.24,82.78 91.21,82.78 89.61,84.38 89.61,88.14 89.82,88.34 92.46,88.34
A_OUT_3 on TOP (solid shape): 127.51,69.95 127.51,68.68 127.46,68.63 124.34,68.63 124.28,68.68 124.28,69.95 124.34,70 127.46,70
A_OUT_3 on TOP (solid shape): 131.8,72.92 134.58,72.9 134.72,72.9 134.86,72.89 135.18,72.89 136.47,72.64 137.58,71.95 137.85,71.68 138.64,70.66 139.14,69.47 139.14,66.88 138.93,66.28 138.38,65.96 137.47,65.96 136.66,66.33 136.4,67.18 136.4,68.4 135.81,69.75 134.42,70.23 134.42,70.23 128.27,70.23 128.15,70.36 128.15,72.8 128.28,72.94 129.85,72.94
A_OUT_3 on BOTTOM (solid shape): 132.9,72.77 132.9,70.13 132.82,70.05 129.31,70.05 127.84,68.58 124.34,68.58 124.26,68.66 124.26,70.71 124.72,71.17 127.13,71.17 128.93,72.97 132.69,72.97
A_OUT_4 on TOP (solid shape): 24.69,45.31 24.69,44.04 24.64,43.99 21.52,43.99 21.47,44.04 21.47,45.31 21.52,45.36 24.64,45.36
A_OUT_4 on TOP (solid shape): 12.58,50.42 12.95,50.29 13.17,49.95 13.17,45.52 13.65,44.36 14.81,43.89 20.78,43.89 20.8,43.87 20.8,41.33 20.67,41.19 18.8,41.19 16.84,41.2 14.06,41.22 13.92,41.23 13.78,41.23 11.7,42.26 10.91,44.45 10.86,49.39 11.15,50.11 11.87,50.42
A_OUT_4 on BOTTOM (solid shape): 24.77,45.39 24.77,43.33 24.31,42.88 21.87,42.88 21.69,42.7 21.69,42.67 20.09,41.07 16.33,41.07 16.13,41.28 16.13,43.92 16.21,43.99 19.71,43.99 21.19,45.47 24.69,45.47
A_OUT_5 on TOP (solid shape): 64.24,82.96 64.24,79.83 64.19,79.78 62.92,79.78 62.87,79.83 62.87,82.96 62.92,83.01 64.19,83.01
A_OUT_5 on TOP (solid shape): 66.27,94.5 66.67,94.4 66.98,94.13 67.02,94.04 67.03,93.94 67.03,92.76 66.83,92.29 66.35,92.13 66,92.13 64.26,92.12 64.2,92.12 64.14,92.11 63.22,91.7 62.77,90.81 62.77,83.79 62.64,83.67 60.17,83.67 60.06,83.78 60.06,85.98 60.07,87.94 60.1,90.72 61.12,93.29 63.62,94.48 63.79,94.5 63.96,94.51
A_OUT_5 on BOTTOM (solid shape): 62.84,88.21 62.84,84.71 64.31,83.24 64.31,79.73 64.24,79.65 62.18,79.65 61.72,80.11 61.72,82.52 59.92,84.33 59.92,88.09 60.12,88.29 62.77,88.29
B_OUT_1 on TOP (solid shape): 41.05,83.11 41.05,79.98 41,79.93 39.73,79.93 39.68,79.98 39.68,83.11 39.73,83.16 41,83.16
B_OUT_1 on TOP (solid shape): 40.08,94.31 40.08,91.26 39.55,90.73 39.55,88.47 39.54,88.46 39.54,83.83 39.47,83.77 37.09,83.77 36.93,83.92 36.93,91.31 37.95,92.33 37.95,94.31 38.1,94.46 39.93,94.46
B_OUT_1 on BOTTOM (solid shape): 39.58,88.44 39.58,84.94 41.05,83.46 41.05,79.96 40.97,79.88 38.91,79.88 38.46,80.34 38.46,82.78 38.28,82.96 38.25,82.96 36.65,84.56 36.65,88.32 36.86,88.52 39.5,88.52
B_OUT_2 on TOP (solid shape): 100.23,82.91 100.23,79.78 100.18,79.73 98.91,79.73 98.86,79.78 98.86,82.91 98.91,82.96 100.18,82.96
B_OUT_2 on TOP (solid shape): 99.21,94.31 99.21,91.26 98.76,90.81 98.76,83.62 98.73,83.59 96.19,83.59 96.06,83.72 96.06,91.16 97.08,92.18 97.08,94.31 97.23,94.46 99.06,94.46
B_OUT_2 on BOTTOM (solid shape): 98.78,88.32 98.78,84.81 100.26,83.34 100.26,79.83 100.18,79.76 98.12,79.76 97.67,80.21 97.67,82.65 97.49,82.83 97.46,82.83 95.86,84.43 95.86,88.19 96.06,88.39 98.71,88.39
B_OUT_3 on TOP (solid shape): 127.43,63.73 127.43,62.46 127.38,62.41 124.26,62.41 124.21,62.46 124.21,63.73 124.26,63.78 127.38,63.78
B_OUT_3 on TOP (solid shape): 136.71,65.51 138.69,65.51 138.84,65.35 138.84,63.53 138.69,63.37 135.64,63.37 135.03,63.98 128.32,63.98 128.12,64.19 128.12,66.47 128.2,66.55 135.66,66.55
B_OUT_3 on BOTTOM (solid shape): 132.87,66.47 132.87,63.83 132.79,63.75 128.68,63.75 127.33,62.41 124.26,62.41 124.21,62.46 124.21,64.57 124.54,64.9 127.23,64.9 129.01,66.68 132.67,66.68
B_OUT_4 on TOP (solid shape): 24.69,51.49 24.69,50.22 24.64,50.17 21.52,50.17 21.47,50.22 21.47,51.49 21.52,51.54 24.64,51.54
B_OUT_4 on TOP (solid shape): 14.79,51.64 14.79,50.37 15.04,50.11 20.7,50.11 20.8,50.01 20.8,47.47 20.6,47.27 19.41,47.27 19.4,47.26 14.3,47.26 13.79,47.77 13.79,50.34 13.11,51.03 11.13,51.03 11.13,51.04 10.99,51.18 10.99,51.64 10.98,51.72 10.97,51.79 10.97,52.71 11.13,52.86 13.57,52.86
B_OUT_4 on BOTTOM (solid shape): 24.77,51.56 24.77,49.5 24.31,49.05 21.87,49.05 21.69,48.87 21.69,48.84 20.09,47.24 16.33,47.24 16.13,47.45 16.13,50.09 16.21,50.17 19.71,50.17 21.19,51.64 24.69,51.64
B_OUT_5 on TOP (solid shape): 70.44,83.01 70.44,79.88 70.39,79.83 69.12,79.83 69.06,79.88 69.06,83.01 69.12,83.06 70.39,83.06
B_OUT_5 on TOP (solid shape): 69.5,94.31 69.5,91.26 68.89,90.65 68.89,83.79 68.76,83.67 66.4,83.67 66.27,83.79 66.27,91.24 67.36,92.33 67.36,94.31 67.52,94.46 69.34,94.46
B_OUT_5 on BOTTOM (solid shape): 69.01,88.32 69.01,84.81 70.49,83.34 70.49,79.83 70.41,79.76 68.35,79.76 67.9,80.21 67.9,82.63 67.9,82.63 66.09,84.43 66.09,88.19 66.3,88.39 68.94,88.39
C_OUT_1 on TOP (solid shape): 47.35,83.06 47.35,79.93 47.3,79.88 46.03,79.88 45.98,79.93 45.98,83.06 46.03,83.11 47.3,83.11
C_OUT_1 on TOP (solid shape): 42.52,94.31 42.52,92.94 45.77,89.69 45.77,83.85 45.7,83.77 43.28,83.77 43.13,83.92 43.13,89.28 40.54,91.87 40.54,94.31 40.69,94.46 42.37,94.46
C_OUT_1 on BOTTOM (solid shape): 45.93,88.39 45.93,84.89 47.4,83.41 47.4,79.91 47.32,79.83 45.27,79.83 44.81,80.29 44.81,82.73 44.63,82.91 44.6,82.91 43,84.51 43,88.26 43.21,88.47 45.85,88.47
C_OUT_2 on TOP (solid shape): 106.43,82.88 106.43,79.76 106.38,79.71 105.11,79.71 105.06,79.76 105.06,82.88 105.11,82.93 106.38,82.93
C_OUT_2 on TOP (solid shape): 101.65,94.31 101.65,92.94 104.9,89.69 104.9,83.59 102.54,83.59 102.32,83.81 102.31,83.81 102.29,89.26 99.67,91.87 99.67,94.31 99.82,94.46 101.5,94.46
C_OUT_2 on BOTTOM (solid shape): 104.95,88.19 104.95,84.68 106.43,83.21 106.43,79.71 106.35,79.63 104.29,79.63 103.84,80.09 103.84,82.52 103.66,82.7 103.63,82.7 102.03,84.3 102.03,88.06 102.24,88.27 104.88,88.27
C_OUT_3 on TOP (solid shape): 127.43,57.48 127.43,56.21 127.38,56.16 124.26,56.16 124.21,56.21 124.21,57.48 124.26,57.53 127.38,57.53
C_OUT_3 on TOP (solid shape): 138.99,62.76 138.99,61.09 138.84,60.93 137.47,60.93 134.24,57.71 128.27,57.71 128.12,57.86 128.12,60.22 128.25,60.35 133.83,60.35 136.4,62.92 138.84,62.92
C_OUT_3 on BOTTOM (solid shape): 132.92,60.27 132.92,57.63 132.84,57.56 128.75,57.56 127.36,56.16 124.26,56.16 124.21,56.21 124.21,57.61 124.25,57.62 124.65,57.93 124.6,58.44 124.59,58.54 124.68,58.6 127.59,58.6 129.47,60.48 132.72,60.48
C_OUT_4 on TOP (solid shape): 24.67,57.71 24.67,56.44 24.61,56.39 21.49,56.39 21.44,56.44 21.44,57.71 21.49,57.76 24.61,57.76
C_OUT_4 on TOP (solid shape): 20.8,56.11 20.8,53.67 20.68,53.54 11.15,53.54 10.97,53.72 10.97,55.3 11.13,55.45 14.02,55.45 14.79,56.21 16.08,56.21 20.73,56.24
C_OUT_4 on BOTTOM (solid shape): 24.67,57.66 24.67,55.6 24.21,55.14 21.77,55.14 21.59,54.97 21.59,54.94 19.99,53.34 16.23,53.34 16.03,53.54 16.03,56.18 16.11,56.26 19.61,56.26 21.08,57.73 24.59,57.73
C_OUT_5 on TOP (solid shape): 76.61,82.98 76.61,79.86 76.56,79.81 75.29,79.81 75.24,79.86 75.24,82.98 75.29,83.03 76.56,83.03
C_OUT_5 on TOP (solid shape): 72.09,94.46 72.09,93.09 75.01,90.17 75.01,83.79 74.91,83.69 72.62,83.69 72.49,83.82 72.49,89.64 70.11,92.02 70.11,94.46 70.26,94.62 71.94,94.62
C_OUT_5 on BOTTOM (solid shape): 75.16,88.32 75.16,84.81 76.63,83.34 76.63,79.83 76.56,79.76 74.5,79.76 74.04,80.21 74.04,82.63 72.24,84.43 72.24,88.19 72.44,88.39 75.08,88.39
Net_2 on TOP (solid shape): 53.82,26.82 62.31,26.82 63.12,26.01 63.12,23.77 62.97,23.62 52.94,23.62 52.25,22.94 45.8,22.94 44.5,24.23 44.5,25.04 45.01,25.55 45.01,29.11 45.29,29.39 51.26,29.39
N16223154 on TOP (solid shape): 51.2,73.47 51.2,56.63 51.76,56.07 54.58,56.07 54.84,55.82 54.84,54.07 54.66,53.89 52.86,53.89 52.58,54.17 52.58,54.65 52.22,55.01 46.1,55.01 46.02,54.93 46.02,54.37 45.95,54.3 44.83,54.3 44.78,54.35 44.78,73.32 45.26,73.8 50.87,73.8
N16231410 on TOP (solid shape): 101.7,88.9 101.7,83.72 101.58,83.59 99.16,83.59 99.05,83.71 99.05,88.28 99.05,88.29 99.05,88.94 99.14,89.03 101.58,89.03
N16231410 on TOP (solid shape): 95.53,88.93 95.53,83.64 95.4,83.59 92.92,83.59 92.86,83.62 92.86,83.72 92.86,88.29 92.86,88.95 92.94,89.03 95.43,89.03
N16231410 on TOP (solid shape): 121.08,92.15 121.08,86.82 121.05,86.74 120.96,86.72 120.33,86.37 120.54,85.68 120.58,85.57 120.48,85.5 118.71,85.5 118.26,85.71 117.82,85.5 109.32,85.5 108.87,85.04 108.87,84.1 108.36,83.59 105.51,83.59 105.26,83.64 105.25,83.79 105.23,88.27 105.23,88.29 105.26,90.07 105.51,90.32 117.73,90.32 118.32,90.91 118.32,91.9 118.7,92.28 120.96,92.28
N16231410 on BOTTOM (solid shape): 109.3,90.55 109.3,85.52 109.12,85.34 105.62,85.34 105.51,85.45 105.51,89.03 105.36,89.18 101.53,89.18 101.37,89.03 101.37,88.98 101.4,88.95 101.4,85.6 101.27,85.47 99.32,85.47 99.14,85.65 99.14,89.05 99.01,89.18 95.38,89.18 95.23,89.03 95.23,85.65 95.18,85.6 92.97,85.6 92.92,85.65 92.92,90.6 93.04,90.73 109.12,90.73
N16232926 on TOP (solid shape): 91.16,82.96 91.16,79.43 91.14,79.4 89.59,79.4 89.54,79.45 89.54,82.93 89.59,82.98 91.14,82.98
N16232926 on TOP (solid shape): 97.33,82.96 97.33,79.43 97.31,79.4 95.76,79.4 95.71,79.45 95.71,82.93 95.76,82.98 97.31,82.98
N16232926 on TOP (solid shape): 103.53,82.96 103.53,79.43 103.51,79.4 101.96,79.4 101.91,79.45 101.91,82.93 101.96,82.98 103.51,82.98
N16232926 on GND (solid shape): outline of 619 points within 89.41,76.86 110.38,84.84
N16233226 on TOP (solid shape): 36.35,89.13 36.35,83.97 36.12,83.74 33.91,83.74 33.66,84 33.66,88.43 33.66,89.13 33.71,89.18 36.3,89.18
N16233226 on TOP (solid shape): 42.57,89.13 42.57,83.97 42.37,83.77 39.93,83.77 39.88,83.82 39.88,89.13 39.98,89.23 42.47,89.23
N16233226 on TOP (solid shape): outline of 169 points within 46.26,76.63 60.05,96.34
N16233226 on BOTTOM (solid shape): 49.41,90.73 49.71,90.42 49.71,85.62 49.53,85.45 46.36,85.45 46.31,85.5 46.31,89.05 46.15,89.2 42.32,89.2 42.17,89.05 42.17,89 42.19,88.98 42.19,85.62 42.06,85.5 40.11,85.5 39.93,85.67 39.93,89.08 39.8,89.2 36.17,89.2 36.02,89.05 36.02,85.67 35.97,85.62 33.76,85.62 33.71,85.67 33.71,90.5 33.94,90.73 48.44,90.73
N16234708 on TOP (solid shape): 32.01,83.08 32.01,79.55 31.98,79.53 30.43,79.53 30.38,79.58 30.38,83.06 30.43,83.11 31.98,83.11
N16234708 on TOP (solid shape): 38.23,83.13 38.23,79.6 38.2,79.58 36.65,79.58 36.6,79.63 36.6,83.11 36.65,83.16 38.2,83.16
N16234708 on TOP (solid shape): 44.43,83.13 44.43,79.6 44.4,79.58 42.85,79.58 42.8,79.63 42.8,83.11 42.85,83.16 44.4,83.16
N16234708 on GND (solid shape): outline of 434 points within 30.25,76.84 51.22,84.81
N16243155 on TOP (solid shape): 20.78,46.69 20.78,44.32 20.66,44.2 15.39,44.25 15.29,44.25 15.22,44.32 15.22,46.76 15.32,46.86 20.6,46.86
N16243155 on TOP (solid shape): 20.78,52.83 20.78,50.52 20.66,50.41 15.43,50.41 15.32,50.52 15.32,52.96 15.45,53.09 20.53,53.09
N16243155 on TOP (solid shape): 20.2,72.47 20.2,66.55 20.19,66.55 20.17,66.38 20.19,66.21 20.2,66.21 20.2,62.89 19.57,62.26 19.56,62.26 19.41,62.15 19.3,62 19.3,61.99 19.23,61.93 19.23,59.77 19.59,59.41 19.61,59.44 20.63,59.44 20.75,59.31 20.75,56.69 20.64,56.6 14.42,56.6 14,57.02 14,68.5 14.12,68.63 16.59,68.63 16.74,68.78 16.74,72.24 17.05,72.54 20.12,72.54
N16243155 on BOTTOM (solid shape): 18.41,59.74 19.23,59.74 19.26,59.72 19.26,56.79 19.18,56.72 15.55,56.72 15.37,56.54 15.37,52.86 15.39,52.83 18.75,52.83 18.87,52.71 18.87,50.75 18.7,50.57 15.65,50.57 15.45,50.37 15.45,46.99 15.78,46.66 18.7,46.66 18.75,46.61 18.75,44.4 18.7,44.35 13.87,44.35 13.64,44.58 13.64,59.59 13.82,59.77 18.41,59.77
N16244549 on TOP (solid shape): 24.95,54.91 24.95,53.37 24.89,53.31 21.41,53.31 21.36,53.37 21.36,54.91 21.39,54.94 24.92,54.94
N16244549 on TOP (solid shape): 25.02,42.49 25.02,40.94 24.97,40.89 21.49,40.89 21.44,40.94 21.44,42.49 21.47,42.52 25,42.52
N16244549 on TOP (solid shape): 25.05,48.72 25.05,47.17 25,47.12 21.52,47.12 21.47,47.17 21.47,48.72 21.49,48.74 25.02,48.74
N16244549 on GND (solid shape): outline of 548 points within 20.27,40.84 27.05,60.85
N16244783 on TOP (solid shape): 133.63,69.65 133.63,67.26 133.53,67.16 128.27,67.16 128.15,67.28 128.15,69.55 128.3,69.7 133.58,69.7
N16244783 on TOP (solid shape): 133.58,63.37 133.58,61.06 133.45,60.93 128.32,60.93 128.15,61.11 128.15,63.37 128.25,63.47 133.48,63.47
N16244783 on TOP (solid shape): 134.34,57.1 134.34,50.34 134.32,50.32 134.32,44.88 134.6,44.6 136.83,44.6 137.06,44.37 137.06,42.16 136.86,41.96 130.05,41.96 129.92,42.09 129.92,46.34 130.1,46.75 129.92,47.16 129.92,48.94 129.99,49.2 129.92,49.47 129.92,51.46 129.98,51.7 129.92,51.94 129.92,54.51 129.75,54.69 128.35,54.69 128.15,54.89 128.15,57.18 128.22,57.25 134.19,57.25
N16244783 on BOTTOM (solid shape): 135.84,69.52 135.84,55.35 135.49,54.99 130.05,54.99 129.95,55.09 129.95,57.15 130,57.2 133.45,57.2 133.78,57.53 133.78,60.99 133.56,61.21 130.2,61.21 130.08,61.34 130.08,63.3 130.25,63.47 133.66,63.47 133.78,63.6 133.78,67.23 133.63,67.39 130.25,67.39 130.2,67.44 130.2,69.65 130.25,69.7 135.66,69.7
N16246163 on TOP (solid shape): 127.46,66.8 127.46,65.25 127.43,65.23 123.9,65.23 123.88,65.25 123.88,66.8 123.93,66.85 127.41,66.85
N16246163 on TOP (solid shape): 127.48,60.6 127.48,59.06 127.46,59.03 123.93,59.03 123.9,59.06 123.9,60.6 123.95,60.66 127.43,60.66
N16246163 on TOP (solid shape): 127.51,73.05 127.51,71.5 127.48,71.48 123.95,71.48 123.93,71.5 123.93,73.05 123.98,73.1 127.46,73.1
N16246163 on GND (solid shape): outline of 484 points within 120.8,54 128.78,73.41
N16248822 on TOP (solid shape): 65.74,89.08 65.74,83.82 65.61,83.69 63.17,83.69 63.07,83.79 63.07,89.1 63.17,89.2 65.61,89.2
N16248822 on TOP (solid shape): 71.91,89.03 71.91,83.92 71.68,83.69 69.34,83.69 69.24,83.79 69.24,88.37 69.24,89.08 69.37,89.2 71.73,89.2
N16248822 on TOP (solid shape): outline of 197 points within 75.44,76.28 90.17,96.77
N16248822 on BOTTOM (solid shape): 79.3,90.96 79.3,85.67 79.12,85.5 75.8,85.5 75.69,85.6 75.69,89.18 75.54,89.33 71.71,89.33 71.55,89.18 71.55,89.13 71.58,89.1 71.58,85.75 71.45,85.62 69.5,85.62 69.32,85.8 69.32,89.2 69.19,89.33 65.56,89.33 65.41,89.18 65.41,85.8 65.36,85.75 63.15,85.75 63.1,85.8 63.1,90.93 63.3,91.14 79.12,91.14
N16249780 on TOP (solid shape): 61.42,83.13 61.42,79.6 61.39,79.58 59.84,79.58 59.79,79.63 59.79,83.11 59.84,83.16 61.39,83.16
N16249780 on TOP (solid shape): 67.72,83.06 67.72,79.53 67.69,79.5 66.14,79.5 66.09,79.55 66.09,83.03 66.14,83.08 67.69,83.08
N16249780 on TOP (solid shape): 73.84,83.11 73.84,79.58 73.81,79.55 72.27,79.55 72.21,79.6 72.21,83.08 72.27,83.13 73.81,83.13
N16249780 on GND (solid shape): outline of 631 points within 59.46,76.63 80.43,84.61

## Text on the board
Ref Des/Silkscreen Bottom: SSLCtrlBrd_V1.0 | 2016/06/20 | PCB-00001
User.Comments: FREQ | NUM | MODE
Board Geometry/Soldermask Top: 16/6/20 | SSL_CtrlBrd | V1_0
DEVICE_TYPE_BOTTOM: FIGURE | SIZE | 0.3556 | 0.4064 | 0.508 | 0.7 | 0.889 | 0.8999 | 0.9652 | 3.81 | 2.032x0.4064 | 3.8608x0.9144 | DRILL CHART: $Drill$ | ALL UNITS ARE IN MILLIMETERS | PLATED | QTY | 288 | 32 | 868 | 5 | 9 | 2 | 65 | 20 | 4 | 3
